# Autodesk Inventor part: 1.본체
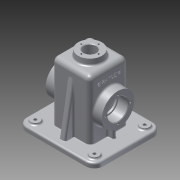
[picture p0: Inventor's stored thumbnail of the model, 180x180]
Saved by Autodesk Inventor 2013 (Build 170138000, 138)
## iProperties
Created: 2016-01
Part Number: 1.본체
Material: 알루미늄 6061
Document SubType Name: Modeling
Designer: Administrator
Density: 2.71 g/cm^3
Mass: 807.486 g
Surface Area: 908.682 cm^2
Volume: 297.965 cm^3
Author: Administrator
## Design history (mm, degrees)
sketch "스케치1"
  geometry: L1 (-65, 57.5)-(65, 57.5); L2 (65, 57.5)-(65, -57.5); L3 (65, -57.5)-(-65, -57.5); L4 (-65, -57.5)-(-65, 57.5); 3 further points
  constraints: 8 end point, 2 midpoint, 2 parallel, 1 horizontal, 1 horizontal alignment, 1 perpendicular, 1 vertical alignment
  dimensions: "d0" = 130 distance of L1.start L1.end; "d2" = 115 distance of L1.end L2.end
extrude "돌출1" new body sketch "스케치1" distance "d3" = 8; taper "d4" = 0 deg
sketch "스케치2"
  geometry: L1 (-32.5, 32.5)-(32.5, 32.5); L2 (32.5, 32.5)-(32.5, -32.5); L3 (32.5, -32.5)-(-32.5, -32.5); L4 (-32.5, -32.5)-(-32.5, 32.5); 3 further points
  constraints: 8 end point, 2 midpoint, 2 parallel, 1 horizontal, 1 horizontal alignment, 1 perpendicular, 1 vertical alignment
  dimensions: "d5" = 65 distance of L1.start L1.end; "d7" = 65 distance of L1.end L2.end
extrude "돌출2" join sketch "스케치2" distance "d8" = 100; taper "d9" = 0 deg
fillet "모깎기1" dims "d10" = 15
sketch "스케치3"
  geometry: C1 r 7.5 at (50, 42.5); C2 r 7.5 at (-50, 42.5); A1 r 15 centre (-50, 42.5) between (-50, 57.5) and (-65, 42.5) reference; A2 r 15 centre (50, 42.5) between (65, 42.5) and (50, 57.5) reference; 1 further point
  constraints: 2 centre point, 2 coincident
  dimensions: "d11" = 7.5 radius of C1; "d12" = 15 diameter of C2
extrude "돌출3" join sketch "스케치3" distance "d13" = 3; taper "d14" = 0 deg
hole "구멍1" diameter "d17" = 5; stored, may be unused: countersink angle "d21" = 90 deg, drill point angle "d23" = 118 deg; dims "d15" = 10, "d16" = 10, "d18" = 6, "d19" = 4, "d20" = 2, "d22" = 8
hole "구멍2" diameter "d26" = 5; stored, may be unused: countersink angle "d30" = 90 deg, drill point angle "d32" = 118 deg; dims "d24" = 10, "d25" = 10, "d27" = 6, "d28" = 4, "d29" = 2, "d31" = 8
sketch "스케치8"
  geometry: L1 (50, 57.5)-(-50, 57.5) reference; L2 (-65, 42.5)-(-65, -42.5) reference; L3 (-50, -57.5)-(50, -57.5) reference; L4 (65, -42.5)-(65, 42.5) reference; L5 (50, -52.5)-(-50, -52.5); L6 (-60, -42.5)-(-60, 42.5); L7 (-50, 52.5)-(50, 52.5); L8 (60, 42.5)-(60, -42.5); C1 r 2.5 at (-50, -42.5) reference; C2 r 2.5 at (50, -42.5) reference; C3 r 2.5 at (50, 42.5) reference; C4 r 2.5 at (-50, 42.5) reference; A1 r 15 centre (50, 42.5) between (65, 42.5) and (50, 57.5) reference; A2 r 15 centre (-50, 42.5) between (-50, 57.5) and (-65, 42.5) reference; A3 r 15 centre (-50, -42.5) between (-65, -42.5) and (-50, -57.5) reference; A4 r 15 centre (50, -42.5) between (50, -57.5) and (65, -42.5) reference; A5 r 10 centre (-50, -42.5) between (-60, -42.5) and (-50, -52.5); A6 r 10 centre (-50, 42.5) between (-50, 52.5) and (-60, 42.5); A7 r 10 centre (50, 42.5) between (60, 42.5) and (50, 52.5); A8 r 10 centre (50, -42.5) between (50, -52.5) and (60, -42.5); 1 further point
  constraints: 8 end point, 8 point on circle, 4 centre point, 7 other
  dimensions: "d52" = 5 distance between parallel lines of L3 L5
extrude "돌출6" join sketch "스케치8" distance "d53" = 2; taper "d54" = 0 deg
sketch "스케치5"
  geometry: C1 r 20 at (0, 0); 1 further point
  constraints: 1 centre point, 1 coincident
  dimensions: "d38" = 40 diameter of C1
extrude "돌출5" join sketch "스케치5" distance "d39" = 10; taper "d40" = 0 deg
feature "면 기울기2" dims angle "d42" = 5 deg
hole "구멍3" diameter "d45" = 21; stored, may be unused: countersink angle "d49" = 90 deg, drill point angle "d51" = 118 deg; dims "d43" = 10, "d44" = 10, "d46" = 6, "d47" = 4, "d48" = 2, "d50" = 8
sketch "스케치9"
  geometry: L1 (27.5, -27.5)-(-27.5, -27.5); L2 (-27.5, -27.5)-(-27.5, 27.5); L3 (-27.5, 27.5)-(27.5, 27.5); L4 (27.5, 27.5)-(27.5, -27.5); C1 r 10.5 at (0, 0) reference; 2 further points
  constraints: 8 end point, 2 midpoint, 2 parallel, 1 horizontal, 1 horizontal alignment, 1 perpendicular, 1 vertical alignment
  dimensions: "d55" = 55 distance of L1.start L1.end; "d57" = 55 distance of L1.end L2.end
extrude "돌출7" cut sketch "스케치9" distance "d58" = 105; taper "d59" = 0 deg
sketch "스케치10"
  geometry: L1 (-32.5, 8)-(-32.5, 108) reference; L2 (-32.5, 108)-(-20.875, 108) reference; L3 (-20.875, 108)-(-20, 118) reference; L4 (-20, 118)-(-10.5, 118) reference; L5 (-10.5, 118)-(-10.5, 103) reference; L6 (-10.5, 103)-(-27.5, 103) reference; L7 (-27.5, 103)-(-27.5, -2) reference; L8 (-27.5, -2)-(-52.5, -2) reference; L9 (-52.5, -2)-(-52.5, 0) reference; L10 (-52.5, 0)-(-57.5, 0) reference; L11 (-57.5, 0)-(-57.5, 8) reference; L12 (-57.5, 8)-(-32.5, 8) reference; L13 (32.5, 108)-(32.5, 8) reference; L14 (32.5, 8)-(57.5, 8) reference; L15 (57.5, 8)-(57.5, 0) reference; L16 (57.5, 0)-(52.5, 0) reference; L17 (52.5, 0)-(52.5, -2) reference; L18 (52.5, -2)-(27.5, -2) reference; L19 (27.5, -2)-(27.5, 103) reference; L20 (27.5, 103)-(10.5, 103) reference; L21 (10.5, 103)-(10.5, 118) reference; L22 (10.5, 118)-(20, 118) reference; L23 (20, 118)-(20.875, 108) reference; L24 (20.875, 108)-(32.5, 108) reference; L25 (-57.5, 8)-(-42.5, 8) reference; L26 (-32.5, 8)-(-32.5, 108) reference; L27 (-32.5, 93.069)-(-47.5, 8); L28 (-32.5, 93.069)-(-32.5, 8); L29 (-32.5, 8)-(-47.5, 8); 1 further point
  constraints: 6 end point, 2 point on line, 1 horizontal, 1 vertical
  dimensions: "d62" = 10 deg angle of L11 L27; "d65" = 10 distance of L11.end L27.end
extrude "돌출8" join sketch "스케치10" stored distance "d63" = 10; taper "d64" = 0 deg
sketch "스케치11"
  geometry: L1 (-60, -2)-(-60, 0) reference; L2 (-60, 0)-(-65, 0) reference; L3 (-65, 0)-(-65, 8) reference; L4 (-65, 8)-(-32.5, 8) reference; L5 (-32.5, 8)-(-32.5, 108) reference; L6 (-32.5, 108)-(-20.875, 108) reference; L7 (-20.875, 108)-(-20, 118) reference; L8 (-20, 118)-(-10.5, 118) reference; L9 (-10.5, 118)-(-10.5, 103) reference; L10 (-10.5, 103)-(-27.5, 103) reference; L11 (-27.5, 103)-(-27.5, -2) reference; L12 (-27.5, -2)-(-60, -2) reference; L13 (60, 0)-(60, -2) reference; L14 (60, -2)-(27.5, -2) reference; L15 (27.5, -2)-(27.5, 103) reference; L16 (27.5, 103)-(10.5, 103) reference; L17 (10.5, 103)-(10.5, 118) reference; L18 (10.5, 118)-(20, 118) reference; L19 (20, 118)-(20.875, 108) reference; L20 (20.875, 108)-(32.5, 108) reference; L21 (32.5, 108)-(32.5, 8) reference; L22 (32.5, 8)-(65, 8) reference; L23 (65, 8)-(65, 0) reference; L24 (65, 0)-(60, 0) reference; L25 (-32.5, 8)-(-42.5, 8); L26 (-42.5, 8)-(-42.5, 53); L27 (-42.5, 53)-(-32.5, 53); L28 (-32.5, 53)-(-32.5, 8); 1 further point
  constraints: 8 end point, 2 parallel, 1 horizontal, 1 perpendicular
  dimensions: "d68" = 15 distance between parallel lines of L11 L26; "d72" = 55 distance between parallel lines of L27 L12
extrude "돌출9" join sketch "스케치11" stored distance "d70" = 6; taper "d71" = 0 deg
sketch "스케치12"
  geometry: L1 (55, 29.5)-(55, 35.5) reference; C1 r 27.5 at (55, 32.5); 1 further point
  constraints: 1 centre point, 1 midpoint
  dimensions: "d73" = 55 diameter of C1
extrude "돌출10" join sketch "스케치12" distance "d74" = 15; taper "d75" = 0 deg
hole "구멍4" diameter "d78" = 30; stored, may be unused: countersink angle "d82" = 90 deg, drill point angle "d84" = 0 deg; dims "d76" = 10, "d77" = 10, "d79" = 6, "d80" = 35, "d81" = 17, "d83" = 20
sketch "스케치13"
  geometry: C1 r 17.5 at (0, 0) reference; 2 further points
  constraints: 1 horizontal alignment
  dimensions: "d85" = 21 distance of C1.centre point (-21, 0)
hole "구멍5" sketch "스케치13" at (-21, 0) diameter "d86" = 3.242; stored, may be unused: countersink angle "d90" = 90 deg, drill point angle "d92" = 118 deg; dims "d87" = 8, "d88" = 35, "d89" = 17, "d91" = 10
sketch "스케치14"
  geometry: C1 r 10.5 at (0, 0) reference; 1 further point
  constraints: 1 horizontal alignment
  dimensions: "d96" = 14.5 distance of C1.centre point (-14.5, 0)
hole "구멍6" sketch "스케치14" at (-14.5, 0) diameter "d97" = 2.459; stored, may be unused: countersink angle "d101" = 90 deg, drill point angle "d103" = 118 deg; dims "d98" = 7, "d99" = 35, "d100" = 17, "d102" = 9
sketch "스케치15"
  geometry: L1 (100, 0)-(0, 0) reference; L2 (110, -20)-(108, -20) reference; L3 (108, -20)-(108, -25) reference; L4 (108, -25)-(100, -25) reference; L5 (100, -25)-(100, 0) reference; L6 (100, 0)-(100, 29.5) reference; L7 (100, 29.5)-(82.336, 29.5) reference; L8 (82.336, 35.5)-(100, 35.5) reference; L9 (100, 35.5)-(100, 65) reference; L10 (100, 65)-(100, 90) reference; L11 (100, 90)-(108, 90) reference; L12 (108, 90)-(108, 85) reference; L13 (108, 85)-(110, 85) reference; L14 (110, 85)-(110, -20) reference; L15 (100, 0)-(0, 0) reference; L16 (0, 0)-(0, 65) reference; L17 (0, 65)-(100, 65) reference; L18 (110, -20)-(108, -20) reference; L19 (108, -20)-(108, -25) reference; L20 (108, -25)-(100, -25) reference; L21 (100, -25)-(100, 0) reference; L22 (100, 0)-(100, 29.5) reference; L23 (100, 29.5)-(82.336, 29.5) reference; L24 (82.336, 35.5)-(100, 35.5) reference; L25 (100, 35.5)-(100, 65) reference; L26 (100, 65)-(100, 90) reference; L27 (100, 90)-(108, 90) reference; L28 (108, 90)-(108, 85) reference; L29 (108, 85)-(110, 85) reference; L30 (110, 85)-(110, -20) reference; L31 (100, 0)-(0, 0) reference; L32 (0, 0)-(0, 65) reference; L33 (0, 65)-(100, 65) reference; L34 (-10, 52.5)-(-10, 12.5) reference; C1 r 17.5 at (55, 32.5) reference; C2 r 17.5 at (55, 32.5) reference; A1 r 27.5 centre (55, 32.5) between (82.336, 35.5) and (82.336, 29.5) reference; A2 r 27.5 centre (55, 32.5) between (82.336, 35.5) and (82.336, 29.5) reference; 2 further points
  constraints: 1 other
  dimensions: "d107" = 27 distance from line of L34 point (17, 32.5); "d108" = 32.5 distance from line of L1 point (17, 32.5)
feature "엠보싱1" sketch "스케치15" dims "d109" = 0.5, "d110" = 0
fillet "모깎기2" dims "d111" = 8
fillet "모깎기3" dims "d112" = 8
fillet "모깎기5" dims "d114" = 3
fillet "모깎기6" dims "d115" = 3
fillet "모깎기7" dims "d116" = 3
fillet "모깎기8" dims "d117" = 3
fillet "모깎기9" dims "d118" = 3
fillet "모깎기10" dims "d119" = 3
fillet "모깎기11" dims "d120" = 3
fillet "모깎기12" dims "d121" = 1
chamfer "모따기1" distance "d122" = 1; stored, may be unused: second distance "d123" = 2, angle "d124" = 45 deg
fillet "모깎기13" dims "d125" = 0.3
fillet "모깎기14" dims "d126" = 3
node "솔리드1"
mirror "대칭1"
mirror "대칭2"
mirror "대칭3"
pattern_circular "원형 패턴1" dims angle "d94" = 360 deg
mirror "대칭4"
pattern_circular "원형 패턴2" dims angle "d105" = 360 deg
node "절단 모서리 투영3"
node "절단 모서리 투영4"
node "절단 모서리 투영5"
node "절단 모서리 투영6"
